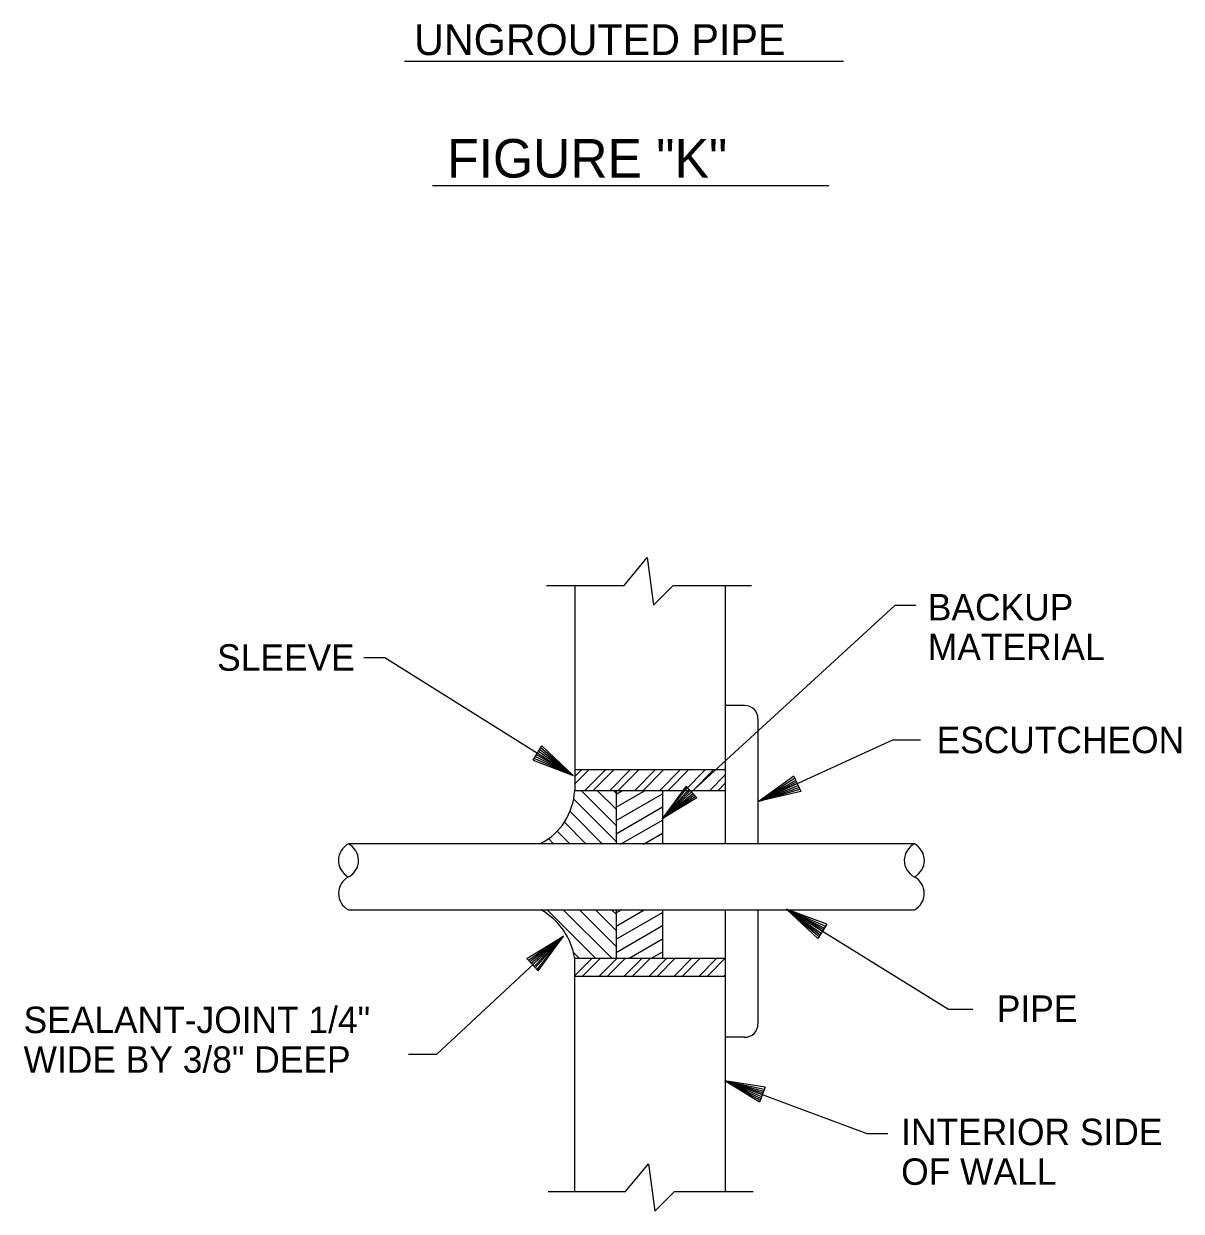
# Model space of a CAD drawing. Extents: x 9999.96 to 10005.26, y 9999.88 to 10002.38.
# Drawn here: x 10001.1276 to 10001.5653, y 10001.489 to 10001.938 of the extents above; entities that cross this region are included whole.
import ezdxf

# ---------------------------------------------------------------- set-up
doc = ezdxf.new("R2010")
doc.units = 0
doc.layers.add('Level 2', color=7, linetype='Continuous')

msp = doc.modelspace()

# ---------------------------------------------------------------- linework, layer by layer
at = {"layer": 'Level 2'}
for p, q in [((10001.43759375, 10001.923833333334), (10001.271625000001, 10001.923833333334)), ((10001.282125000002, 10001.876833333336), (10001.432052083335, 10001.876833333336)), ((10001.336000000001, 10001.725666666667), (10001.336000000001, 10001.648052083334)), ((10001.392843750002, 10001.725666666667), (10001.392843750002, 10001.627916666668)), ((10001.400208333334, 10001.680302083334), (10001.392843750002, 10001.680302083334)), ((10001.405270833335, 10001.675239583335), (10001.405270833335, 10001.628020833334)), ((10001.320187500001, 10001.659583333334), (10001.323572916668, 10001.664968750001)), ((10001.321843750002, 10001.662260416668), (10001.335333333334, 10001.653833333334)), ((10001.335333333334, 10001.653833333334), (10001.32228125, 10001.662927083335)), ((10001.335333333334, 10001.653833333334), (10001.322687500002, 10001.663604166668)), ((10001.335333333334, 10001.653833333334), (10001.323104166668, 10001.664239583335)), ((10001.323572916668, 10001.664968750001), (10001.335333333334, 10001.653833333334)), ((10001.320187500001, 10001.659583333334), (10001.335333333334, 10001.653833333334)), ((10001.335333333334, 10001.653833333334), (10001.320614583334, 10001.660270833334)), ((10001.335333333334, 10001.653833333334), (10001.321062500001, 10001.661031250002)), ((10001.335333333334, 10001.653833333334), (10001.321458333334, 10001.661625)), ((10001.335927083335, 10001.653343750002), (10001.338562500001, 10001.655979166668)), ((10001.392843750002, 10001.655958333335), (10001.335947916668, 10001.655958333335)), ((10001.335979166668, 10001.650708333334), (10001.341250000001, 10001.655958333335)), ((10001.339635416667, 10001.648052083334), (10001.347541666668, 10001.655958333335)), ((10001.342781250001, 10001.648052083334), (10001.350697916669, 10001.655958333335)), ((10001.349083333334, 10001.648052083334), (10001.356989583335, 10001.655958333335)), ((10001.352239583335, 10001.648052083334), (10001.360145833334, 10001.655958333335)), ((10001.358531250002, 10001.648052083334), (10001.3664375, 10001.655958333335)), ((10001.361697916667, 10001.648052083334), (10001.369593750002, 10001.655958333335)), ((10001.367989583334, 10001.648052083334), (10001.375885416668, 10001.655958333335)), ((10001.371145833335, 10001.648052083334), (10001.379052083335, 10001.655958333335)), ((10001.377437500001, 10001.648052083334), (10001.385343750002, 10001.655958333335)), ((10001.380593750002, 10001.648052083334), (10001.388500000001, 10001.655958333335)), ((10001.386885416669, 10001.648052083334), (10001.392843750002, 10001.654010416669)), ((10001.418802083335, 10001.653572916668), (10001.405666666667, 10001.644093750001)), ((10001.405666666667, 10001.644093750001), (10001.419135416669, 10001.652843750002)), ((10001.418802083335, 10001.653572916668), (10001.421437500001, 10001.647791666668)), ((10001.378125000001, 10001.649802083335), (10001.369052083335, 10001.637416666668)), ((10001.369052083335, 10001.637416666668), (10001.378645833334, 10001.649239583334)), ((10001.369052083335, 10001.637416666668), (10001.379229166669, 10001.648625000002)), ((10001.378125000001, 10001.649802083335), (10001.382187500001, 10001.645354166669)), ((10001.390041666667, 10001.648052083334), (10001.392843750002, 10001.650854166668)), ((10001.405666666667, 10001.644093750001), (10001.419531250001, 10001.652041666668)), ((10001.405666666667, 10001.644093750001), (10001.419802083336, 10001.651385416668)), ((10001.420125, 10001.650718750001), (10001.405666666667, 10001.644093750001)), ((10001.405666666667, 10001.644093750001), (10001.4204375, 10001.649989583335)), ((10001.405666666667, 10001.644093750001), (10001.42078125, 10001.649281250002)), ((10001.405666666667, 10001.644093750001), (10001.421083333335, 10001.648583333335)), ((10001.351583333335, 10001.62884375), (10001.335468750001, 10001.644958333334)), ((10001.392843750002, 10001.648052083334), (10001.335947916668, 10001.648052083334)), ((10001.351583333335, 10001.634947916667), (10001.338479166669, 10001.648052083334)), ((10001.351583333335, 10001.6410625), (10001.344614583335, 10001.64803125)), ((10001.351583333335, 10001.647177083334), (10001.350729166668, 10001.648020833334)), ((10001.351583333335, 10001.648020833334), (10001.351583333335, 10001.627781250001)), ((10001.351583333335, 10001.641770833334), (10001.362406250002, 10001.648020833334)), ((10001.351583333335, 10001.646760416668), (10001.353760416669, 10001.648020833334)), ((10001.351583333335, 10001.636781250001), (10001.369145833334, 10001.646927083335)), ((10001.369052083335, 10001.637416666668), (10001.379666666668, 10001.648125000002)), ((10001.380145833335, 10001.647614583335), (10001.369052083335, 10001.637416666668)), ((10001.369052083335, 10001.637416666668), (10001.380645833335, 10001.647041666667)), ((10001.369052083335, 10001.637416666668), (10001.381156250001, 10001.6465)), ((10001.369052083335, 10001.637416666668), (10001.381645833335, 10001.645958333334)), ((10001.382187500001, 10001.645354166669), (10001.369052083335, 10001.637416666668)), ((10001.369145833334, 10001.648020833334), (10001.369145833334, 10001.627781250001)), ((10001.421437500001, 10001.647791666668), (10001.405666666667, 10001.644093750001)), ((10001.346489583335, 10001.62784375), (10001.334062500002, 10001.640250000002)), ((10001.351583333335, 10001.631802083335), (10001.369145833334, 10001.641927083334)), ((10001.340322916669, 10001.627895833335), (10001.331958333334, 10001.636260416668)), ((10001.353270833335, 10001.627781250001), (10001.369145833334, 10001.636958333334)), ((10001.334145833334, 10001.627958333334), (10001.32925, 10001.632843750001)), ((10001.361916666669, 10001.627781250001), (10001.369145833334, 10001.631968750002)), ((10001.464395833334, 10001.627916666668), (10001.250395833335, 10001.627916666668)), ((10001.327979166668, 10001.628010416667), (10001.325989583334, 10001.629989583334)), ((10001.250395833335, 10001.603000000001), (10001.464395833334, 10001.603000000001)), ((10001.343770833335, 10001.584729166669), (10001.325552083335, 10001.602947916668)), ((10001.3498125, 10001.584791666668), (10001.331635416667, 10001.602968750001)), ((10001.351583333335, 10001.589135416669), (10001.337718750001, 10001.602989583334)), ((10001.351583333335, 10001.595239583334), (10001.343812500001, 10001.603020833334)), ((10001.351583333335, 10001.60134375), (10001.349895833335, 10001.60303125)), ((10001.351583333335, 10001.60303125), (10001.351583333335, 10001.584812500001)), ((10001.351583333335, 10001.596875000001), (10001.362250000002, 10001.60303125)), ((10001.351583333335, 10001.601875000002), (10001.353604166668, 10001.60303125)), ((10001.351583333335, 10001.591895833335), (10001.369145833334, 10001.60203125)), ((10001.369145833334, 10001.60303125), (10001.369145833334, 10001.584645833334)), ((10001.392843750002, 10001.603000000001), (10001.392843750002, 10001.496437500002)), ((10001.405270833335, 10001.603114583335), (10001.405270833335, 10001.559864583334)), ((10001.429625, 10001.594895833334), (10001.416093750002, 10001.603250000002)), ((10001.42790625, 10001.592177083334), (10001.416093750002, 10001.603250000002)), ((10001.431270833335, 10001.597572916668), (10001.416093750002, 10001.603250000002)), ((10001.416093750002, 10001.603250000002), (10001.428791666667, 10001.593541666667)), ((10001.416093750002, 10001.603250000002), (10001.430395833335, 10001.596114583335)), ((10001.416093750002, 10001.603250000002), (10001.428375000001, 10001.592906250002)), ((10001.416093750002, 10001.603250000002), (10001.429187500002, 10001.59421875)), ((10001.416093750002, 10001.603250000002), (10001.430000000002, 10001.595531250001)), ((10001.416093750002, 10001.603250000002), (10001.430843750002, 10001.596885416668)), ((10001.351583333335, 10001.58690625), (10001.369145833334, 10001.597041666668)), ((10001.431270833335, 10001.597572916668), (10001.42790625, 10001.592177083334)), ((10001.317875, 10001.584541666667), (10001.331677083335, 10001.593020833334)), ((10001.331677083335, 10001.593020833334), (10001.318458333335, 10001.583895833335)), ((10001.331677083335, 10001.593020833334), (10001.318968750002, 10001.583333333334)), ((10001.331677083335, 10001.593020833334), (10001.319510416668, 10001.582760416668)), ((10001.320052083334, 10001.582177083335), (10001.331677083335, 10001.593020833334)), ((10001.331677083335, 10001.593020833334), (10001.320562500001, 10001.581635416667)), ((10001.331677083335, 10001.593020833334), (10001.321031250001, 10001.581104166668)), ((10001.331677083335, 10001.593020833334), (10001.321645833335, 10001.580468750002)), ((10001.322197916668, 10001.579875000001), (10001.331677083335, 10001.593020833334)), ((10001.356510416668, 10001.584760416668), (10001.369145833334, 10001.592052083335)), ((10001.337718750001, 10001.584656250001), (10001.335364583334, 10001.587010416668)), ((10001.365000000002, 10001.584677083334), (10001.369145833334, 10001.587072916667)), ((10001.322197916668, 10001.579875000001), (10001.317875, 10001.584541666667)), ((10001.392843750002, 10001.584645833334), (10001.335947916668, 10001.584645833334)), ((10001.335947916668, 10001.578208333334), (10001.342385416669, 10001.584645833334)), ((10001.336000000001, 10001.496437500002), (10001.336000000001, 10001.584645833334)), ((10001.336000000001, 10001.584552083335), (10001.336083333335, 10001.584645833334)), ((10001.338864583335, 10001.577979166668), (10001.345531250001, 10001.584645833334)), ((10001.345166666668, 10001.577979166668), (10001.351833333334, 10001.584645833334)), ((10001.348312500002, 10001.577979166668), (10001.354979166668, 10001.584645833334)), ((10001.354614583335, 10001.577979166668), (10001.361281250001, 10001.584645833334)), ((10001.357770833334, 10001.577979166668), (10001.364437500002, 10001.584645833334)), ((10001.3640625, 10001.577979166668), (10001.370729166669, 10001.584645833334)), ((10001.367218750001, 10001.577979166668), (10001.373885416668, 10001.584645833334)), ((10001.373520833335, 10001.577979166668), (10001.3801875, 10001.584645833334)), ((10001.376666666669, 10001.577979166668), (10001.383333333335, 10001.584645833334)), ((10001.382968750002, 10001.577979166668), (10001.389635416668, 10001.584645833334)), ((10001.386114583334, 10001.577979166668), (10001.39278125, 10001.584645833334)), ((10001.335947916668, 10001.577979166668), (10001.392843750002, 10001.577979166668)), ((10001.392416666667, 10001.577979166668), (10001.392843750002, 10001.578395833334)), ((10001.400208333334, 10001.554802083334), (10001.392843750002, 10001.554802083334)), ((10001.406895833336, 10001.533114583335), (10001.392770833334, 10001.538354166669)), ((10001.405812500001, 10001.530270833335), (10001.392770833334, 10001.538354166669)), ((10001.407927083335, 10001.535906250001), (10001.392770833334, 10001.538354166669)), ((10001.392770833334, 10001.538354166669), (10001.406375, 10001.531708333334)), ((10001.392770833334, 10001.538354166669), (10001.407385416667, 10001.534395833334)), ((10001.392770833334, 10001.538354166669), (10001.406104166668, 10001.53103125)), ((10001.392770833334, 10001.538354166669), (10001.406625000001, 10001.532406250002)), ((10001.392770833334, 10001.538354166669), (10001.407135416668, 10001.533770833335)), ((10001.392770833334, 10001.538354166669), (10001.407656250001, 10001.535187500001)), ((10001.407927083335, 10001.535906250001), (10001.405812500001, 10001.530270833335))]:
    msp.add_line(p, q, dxfattribs=at)
for points in [[(10001.32534375, 10001.725666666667), (10001.354645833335, 10001.725666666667), (10001.363385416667, 10001.736177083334), (10001.365739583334, 10001.718260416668), (10001.373166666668, 10001.725666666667), (10001.402875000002, 10001.725666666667)], [(10001.464958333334, 10001.718041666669), (10001.457052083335, 10001.718041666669), (10001.369052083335, 10001.637416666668)], [(10001.256197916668, 10001.698395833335), (10001.264177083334, 10001.698395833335), (10001.335333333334, 10001.653833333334)], [(10001.466718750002, 10001.667125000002), (10001.456083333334, 10001.667125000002), (10001.405666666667, 10001.644093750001)], [(10001.486583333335, 10001.56534375), (10001.477270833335, 10001.56534375), (10001.416093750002, 10001.603250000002)], [(10001.273156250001, 10001.548468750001), (10001.283791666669, 10001.548468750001), (10001.331677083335, 10001.593020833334)], [(10001.454416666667, 10001.518322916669), (10001.446520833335, 10001.518322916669), (10001.392770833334, 10001.538354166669)], [(10001.325864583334, 10001.496437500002), (10001.355166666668, 10001.496437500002), (10001.36390625, 10001.506947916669), (10001.366260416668, 10001.489031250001), (10001.373687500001, 10001.496437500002), (10001.403395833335, 10001.496437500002)]]:
    msp.add_lwpolyline(points, dxfattribs=at)
for centre, radius, start, end in [((10001.400207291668, 10001.67523979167), 0.005062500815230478, 0, 90), ((10001.311995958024, 10001.649325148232), 0.023982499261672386, 297.50966666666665, 356.963775), ((10001.253628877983, 10001.62167967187), 0.007020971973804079, 117.38482499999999, 241.91503055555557), ((10001.247170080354, 10001.62167967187), 0.007020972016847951, 298.0849694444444, 62.615175), ((10001.467629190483, 10001.62167967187), 0.007020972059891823, 117.38482499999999, 241.91503055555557), ((10001.461170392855, 10001.62167967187), 0.007020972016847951, 298.0849694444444, 62.615175), ((10001.253701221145, 10001.609229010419), 0.0070518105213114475, 117.91829444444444, 242.08170833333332), ((10001.461098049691, 10001.609229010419), 0.007051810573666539, 297.9182916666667, 62.08170555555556), ((10001.310739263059, 10001.580696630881), 0.02551343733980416, 8.91205, 60.69234722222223), ((10001.400207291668, 10001.55986541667), 0.005062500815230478, 270, 0)]:
    msp.add_arc(centre, radius, start, end, dxfattribs=at)

# ---------------------------------------------------------------- texts
for s, height, p in [('UNGROUTED PIPE', 0.011666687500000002, (10001.275229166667, 10001.926208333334)), ('FIGURE "K"', 0.014583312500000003, (10001.287697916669, 10001.879864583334)), ('BACKUP', 0.010000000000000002, (10001.469510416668, 10001.712416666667)), ('MATERIAL', 0.010000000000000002, (10001.469510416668, 10001.697416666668)), ('SLEEVE', 0.010000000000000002, (10001.200729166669, 10001.69340625)), ('ESCUTCHEON', 0.010000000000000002, (10001.472822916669, 10001.662239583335)), ('PIPE', 0.010000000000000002, (10001.495604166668, 10001.560635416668)), ('SEALANT-JOINT 1/4"', 0.010000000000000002, (10001.127531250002, 10001.556406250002)), ('WIDE BY 3/8" DEEP', 0.010000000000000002, (10001.127531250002, 10001.541406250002)), ('INTERIOR SIDE', 0.010000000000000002, (10001.459416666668, 10001.514020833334)), ('OF WALL', 0.010000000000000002, (10001.459416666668, 10001.499020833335))]:
    msp.add_text(s, height=height, dxfattribs=at).set_placement(p)

doc.saveas('drawing.dxf')
